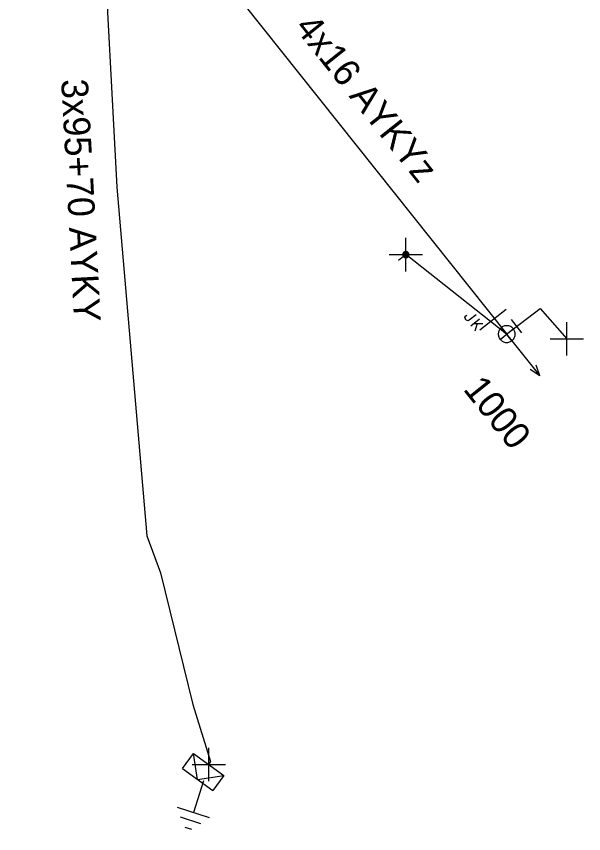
# Model space of a CAD drawing. Extents: x -540247 to -537390, y -1183887 to -1180355.
# Drawn here: x -537477.06 to -537455.83, y -1180665.57 to -1180635 of the extents above; entities that cross this region are included whole.
import ezdxf

# ---------------------------------------------------------------- set-up
doc = ezdxf.new("R2010")
doc.units = 0
for name, color, linetype in [('Vrstva 1', 7, 'Continuous'), ('Vrstva 13', 7, 'Continuous'), ('Vrstva 14', 7, 'Continuous'), ('Vrstva 15', 7, 'Continuous'), ('Vrstva 18', 7, 'Continuous'), ('Vrstva 2', 7, 'Continuous'), ('Vrstva 31', 7, 'Continuous'), ('Vrstva 34', 7, 'Continuous'), ('Vrstva 4', 7, 'Continuous'), ('Vrstva 52', 7, 'Continuous'), ('Vrstva 53', 7, 'Continuous'), ('Vrstva 54', 7, 'Continuous'), ('Vrstva 9', 7, 'Continuous')]:
    doc.layers.add(name, color=color, linetype=linetype)

# ---------------------------------------------------------------- blocks, each defined once
blk = doc.blocks.new('NN560')
at = {"layer": 'Vrstva 2'}
for points in [[(1.999, -0.001), (1.59, 0.141)], [(0, -0.001), (1.999, -0.001)], [(1.999, -0.001), (1.59, -0.134)]]:
    blk.add_lwpolyline(points, dxfattribs=at)
blk = doc.blocks.new('NN840')
at = {"layer": 'Vrstva 15'}
for points in [[(0.003, 0.619), (0.003, -0.631)], [(-0.538, -0.385), (-0.538, -0.71)], [(-0.332, -0.385), (-0.332, -0.798)], [(-0.332, -0.641), (-0.125, -0.385)], [(-0.263, -0.557), (-0.091, -0.798)], [(-0.745, -0.71), (-0.745, -0.66)], [(-0.73, -0.764), (-0.745, -0.71)], [(-0.657, -0.798), (-0.73, -0.764)], [(-0.627, -0.798), (-0.657, -0.798)], [(-0.558, -0.764), (-0.627, -0.798)], [(-0.538, -0.71), (-0.558, -0.764)]]:
    blk.add_lwpolyline(points, dxfattribs=at)
blk = doc.blocks.new('NN800')
at = {"layer": 'Vrstva 1'}
for points in [[(-0.442, 0.442), (0.442, -0.442)], [(-0.442, -0.442), (0.442, 0.442)]]:
    blk.add_lwpolyline(points, dxfattribs=at)
blk = doc.blocks.new('NN630')
at = {"layer": 'Vrstva 9'}
for points in [[(-0.003, -0.7), (-0.703, 0)], [(-0.703, -0.7), (-0.703, 0), (0.697, 0), (0.697, -0.7)], [(-0.003, -0.7), (0.697, 0)], [(-0.703, -0.7), (0.697, -0.7)]]:
    blk.add_lwpolyline(points, dxfattribs=at)
blk = doc.blocks.new('NN810')
at = {"layer": 'Vrstva 14'}
for points in [[(0.004, -0.64), (0.004, -1.89)], [(0.629, -1.89), (-0.621, -1.89)], [(0.388, -2.2), (-0.399, -2.2)], [(0.004, -2.515), (-0.124, -2.515)], [(0.137, -2.515), (0.004, -2.515)]]:
    blk.add_lwpolyline(points, dxfattribs=at)
blk = doc.blocks.new('NN500')
at = {"layer": 'Vrstva 2'}
for points in [[(-0.001, -0.235), (0.023, -0.234), (0.048, -0.23), (0.071, -0.224), (0.094, -0.215), (0.116, -0.204), (0.137, -0.191), (0.156, -0.175), (0.173, -0.158), (0.189, -0.139), (0.202, -0.118), (0.213, -0.096), (0.222, -0.073), (0.229, -0.049), (0.232, -0.025), (0.234, 0), (0.232, 0.024), (0.229, 0.048), (0.222, 0.072), (0.213, 0.095), (0.202, 0.117), (0.189, 0.138), (0.173, 0.157), (0.156, 0.174), (0.137, 0.19), (0.116, 0.203), (0.094, 0.214), (0.071, 0.223), (0.048, 0.229), (0.023, 0.233), (-0.001, 0.235), (-0.026, 0.233), (-0.05, 0.229), (-0.074, 0.223), (-0.097, 0.214), (-0.119, 0.203), (-0.139, 0.19), (-0.158, 0.174), (-0.176, 0.157), (-0.191, 0.138), (-0.205, 0.117), (-0.216, 0.095), (-0.225, 0.072), (-0.231, 0.048), (-0.235, 0.024), (-0.236, 0), (-0.235, -0.025), (-0.231, -0.049), (-0.225, -0.073), (-0.216, -0.096), (-0.205, -0.118), (-0.191, -0.139), (-0.176, -0.158), (-0.158, -0.175), (-0.139, -0.191), (-0.119, -0.204), (-0.097, -0.215), (-0.074, -0.224), (-0.05, -0.23), (-0.026, -0.234), (-0.001, -0.235)], [(-0.001, -0.235), (0.023, -0.234), (0.048, -0.23), (0.071, -0.224), (0.094, -0.215), (0.116, -0.204), (0.137, -0.191), (0.156, -0.175), (0.173, -0.158), (0.189, -0.139), (0.202, -0.118), (0.213, -0.096), (0.222, -0.073), (0.229, -0.049), (0.232, -0.025), (0.234, 0), (0.232, 0.024), (0.229, 0.048), (0.222, 0.072), (0.213, 0.095), (0.202, 0.117), (0.189, 0.138), (0.173, 0.157), (0.156, 0.174), (0.137, 0.19), (0.116, 0.203), (0.094, 0.214), (0.071, 0.223), (0.048, 0.229), (0.023, 0.233), (-0.001, 0.235), (-0.026, 0.233), (-0.05, 0.229), (-0.074, 0.223), (-0.097, 0.214), (-0.119, 0.203), (-0.139, 0.19), (-0.158, 0.174), (-0.176, 0.157), (-0.191, 0.138), (-0.205, 0.117), (-0.216, 0.095), (-0.225, 0.072), (-0.231, 0.048), (-0.235, 0.024), (-0.236, 0), (-0.235, -0.025), (-0.231, -0.049), (-0.225, -0.073), (-0.216, -0.096), (-0.205, -0.118), (-0.191, -0.139), (-0.176, -0.158), (-0.158, -0.175), (-0.139, -0.191), (-0.119, -0.204), (-0.097, -0.215), (-0.074, -0.224), (-0.05, -0.23), (-0.026, -0.234), (-0.001, -0.235)], [(-0.001, -0.206), (0.02, -0.205), (0.041, -0.201), (0.062, -0.196), (0.082, -0.188), (0.101, -0.178), (0.12, -0.167), (0.136, -0.153), (0.151, -0.138), (0.165, -0.121), (0.177, -0.103), (0.186, -0.084), (0.194, -0.064), (0.2, -0.043), (0.203, -0.022), (0.204, 0), (0.203, 0.021), (0.2, 0.042), (0.194, 0.063), (0.186, 0.083), (0.177, 0.102), (0.165, 0.12), (0.151, 0.137), (0.136, 0.152), (0.12, 0.166), (0.101, 0.177), (0.082, 0.187), (0.062, 0.195), (0.041, 0.2), (0.02, 0.204), (-0.001, 0.205), (-0.023, 0.204), (-0.044, 0.2), (-0.065, 0.195), (-0.085, 0.187), (-0.104, 0.177), (-0.122, 0.166), (-0.139, 0.152), (-0.154, 0.137), (-0.167, 0.12), (-0.179, 0.102), (-0.189, 0.083), (-0.197, 0.063), (-0.202, 0.042), (-0.205, 0.021), (-0.207, 0), (-0.205, -0.022), (-0.202, -0.043), (-0.197, -0.064), (-0.189, -0.084), (-0.179, -0.103), (-0.167, -0.121), (-0.154, -0.138), (-0.139, -0.153), (-0.122, -0.167), (-0.104, -0.178), (-0.085, -0.188), (-0.065, -0.196), (-0.044, -0.201), (-0.023, -0.205), (-0.001, -0.206)], [(-0.001, -0.176), (0.017, -0.175), (0.035, -0.172), (0.053, -0.168), (0.07, -0.161), (0.087, -0.153), (0.102, -0.143), (0.116, -0.131), (0.129, -0.118), (0.141, -0.104), (0.151, -0.088), (0.159, -0.072), (0.166, -0.055), (0.171, -0.037), (0.174, -0.019), (0.175, 0), (0.174, 0.018), (0.171, 0.036), (0.166, 0.054), (0.159, 0.071), (0.151, 0.087), (0.141, 0.103), (0.129, 0.117), (0.116, 0.13), (0.102, 0.142), (0.087, 0.152), (0.07, 0.16), (0.053, 0.167), (0.035, 0.172), (0.017, 0.174), (-0.001, 0.175), (-0.02, 0.174), (-0.038, 0.172), (-0.056, 0.167), (-0.073, 0.16), (-0.089, 0.152), (-0.105, 0.142), (-0.119, 0.13), (-0.132, 0.117), (-0.143, 0.103), (-0.153, 0.087), (-0.162, 0.071), (-0.168, 0.054), (-0.173, 0.036), (-0.176, 0.018), (-0.177, 0), (-0.176, -0.019), (-0.173, -0.037), (-0.168, -0.055), (-0.162, -0.072), (-0.153, -0.088), (-0.143, -0.104), (-0.132, -0.118), (-0.119, -0.131), (-0.105, -0.143), (-0.089, -0.153), (-0.073, -0.161), (-0.056, -0.168), (-0.038, -0.172), (-0.02, -0.175), (-0.001, -0.176)], [(-0.001, -0.147), (0.014, -0.146), (0.029, -0.143), (0.044, -0.139), (0.058, -0.134), (0.072, -0.127), (0.085, -0.119), (0.097, -0.109), (0.107, -0.098), (0.117, -0.086), (0.125, -0.073), (0.132, -0.06), (0.138, -0.046), (0.142, -0.031), (0.144, -0.016), (0.145, 0), (0.144, 0.015), (0.142, 0.03), (0.138, 0.045), (0.132, 0.059), (0.125, 0.073), (0.117, 0.086), (0.107, 0.097), (0.097, 0.108), (0.085, 0.118), (0.072, 0.126), (0.058, 0.133), (0.044, 0.139), (0.029, 0.143), (0.014, 0.145), (-0.001, 0.146), (-0.017, 0.145), (-0.032, 0.143), (-0.046, 0.139), (-0.061, 0.133), (-0.074, 0.126), (-0.087, 0.118), (-0.099, 0.108), (-0.11, 0.097), (-0.119, 0.086), (-0.128, 0.073), (-0.135, 0.059), (-0.14, 0.045), (-0.144, 0.03), (-0.147, 0.015), (-0.147, 0), (-0.147, -0.016), (-0.144, -0.031), (-0.14, -0.046), (-0.135, -0.06), (-0.128, -0.073), (-0.119, -0.086), (-0.11, -0.098), (-0.099, -0.109), (-0.087, -0.119), (-0.074, -0.127), (-0.061, -0.134), (-0.046, -0.139), (-0.032, -0.143), (-0.017, -0.146), (-0.001, -0.147)], [(-0.001, -0.117), (0.011, -0.116), (0.023, -0.114), (0.035, -0.111), (0.046, -0.107), (0.057, -0.101), (0.067, -0.095), (0.077, -0.087), (0.085, -0.078), (0.093, -0.069), (0.1, -0.059), (0.105, -0.048), (0.11, -0.036), (0.113, -0.025), (0.115, -0.013), (0.115, 0), (0.115, 0.012), (0.113, 0.024), (0.11, 0.036), (0.105, 0.047), (0.1, 0.058), (0.093, 0.068), (0.085, 0.078), (0.077, 0.086), (0.067, 0.094), (0.057, 0.101), (0.046, 0.106), (0.035, 0.11), (0.023, 0.114), (0.011, 0.116), (-0.001, 0.116), (-0.013, 0.116), (-0.025, 0.114), (-0.037, 0.11), (-0.049, 0.106), (-0.059, 0.101), (-0.07, 0.094), (-0.079, 0.086), (-0.088, 0.078), (-0.096, 0.068), (-0.102, 0.058), (-0.108, 0.047), (-0.112, 0.036), (-0.115, 0.024), (-0.117, 0.012), (-0.118, 0), (-0.117, -0.013), (-0.115, -0.025), (-0.112, -0.036), (-0.108, -0.048), (-0.102, -0.059), (-0.096, -0.069), (-0.088, -0.078), (-0.079, -0.087), (-0.07, -0.095), (-0.059, -0.101), (-0.049, -0.107), (-0.037, -0.111), (-0.025, -0.114), (-0.013, -0.116), (-0.001, -0.117)], [(-0.001, -0.087), (0.008, -0.087), (0.017, -0.085), (0.026, -0.083), (0.034, -0.08), (0.042, -0.076), (0.05, -0.071), (0.057, -0.065), (0.063, -0.059), (0.069, -0.051), (0.074, -0.044), (0.078, -0.036), (0.081, -0.027), (0.084, -0.019), (0.085, -0.01), (0.086, 0), (0.085, 0.009), (0.084, 0.018), (0.081, 0.026), (0.078, 0.035), (0.074, 0.043), (0.069, 0.051), (0.063, 0.058), (0.057, 0.064), (0.05, 0.07), (0.042, 0.075), (0.034, 0.079), (0.026, 0.082), (0.017, 0.085), (0.008, 0.086), (-0.001, 0.087), (-0.01, 0.086), (-0.019, 0.085), (-0.028, 0.082), (-0.037, 0.079), (-0.045, 0.075), (-0.052, 0.07), (-0.059, 0.064), (-0.066, 0.058), (-0.072, 0.051), (-0.077, 0.043), (-0.081, 0.035), (-0.084, 0.026), (-0.086, 0.018), (-0.088, 0.009), (-0.088, 0), (-0.088, -0.01), (-0.086, -0.019), (-0.084, -0.027), (-0.081, -0.036), (-0.077, -0.044), (-0.072, -0.052), (-0.066, -0.059), (-0.059, -0.065), (-0.052, -0.071), (-0.045, -0.076), (-0.037, -0.08), (-0.028, -0.083), (-0.019, -0.085), (-0.01, -0.087), (-0.001, -0.087)], [(-0.001, -0.058), (0.005, -0.057), (0.011, -0.056), (0.016, -0.055), (0.022, -0.053), (0.027, -0.05), (0.032, -0.047), (0.037, -0.043), (0.041, -0.039), (0.045, -0.034), (0.048, -0.029), (0.051, -0.024), (0.053, -0.018), (0.055, -0.012), (0.056, -0.006), (0.056, 0), (0.056, 0.006), (0.055, 0.011), (0.053, 0.017), (0.051, 0.023), (0.048, 0.028), (0.045, 0.033), (0.041, 0.038), (0.037, 0.042), (0.032, 0.046), (0.027, 0.049), (0.022, 0.052), (0.016, 0.054), (0.011, 0.056), (0.005, 0.057), (-0.001, 0.057), (-0.007, 0.057), (-0.013, 0.056), (-0.019, 0.054), (-0.025, 0.052), (-0.03, 0.049), (-0.035, 0.046), (-0.04, 0.042), (-0.044, 0.038), (-0.048, 0.033), (-0.051, 0.028), (-0.054, 0.023), (-0.056, 0.017), (-0.057, 0.011), (-0.058, 0.006), (-0.059, 0), (-0.058, -0.006), (-0.057, -0.012), (-0.056, -0.018), (-0.054, -0.024), (-0.051, -0.029), (-0.048, -0.034), (-0.044, -0.039), (-0.04, -0.043), (-0.035, -0.047), (-0.03, -0.05), (-0.025, -0.053), (-0.019, -0.055), (-0.013, -0.056), (-0.007, -0.057), (-0.001, -0.058)], [(-0.001, -0.028), (0.002, -0.028), (0.005, -0.028), (0.007, -0.027), (0.01, -0.026), (0.013, -0.024), (0.015, -0.023), (0.017, -0.021), (0.019, -0.019), (0.021, -0.017), (0.023, -0.014), (0.024, -0.012), (0.025, -0.009), (0.026, -0.006), (0.026, -0.003), (0.027, 0), (0.026, 0.002), (0.026, 0.005), (0.025, 0.008), (0.024, 0.011), (0.023, 0.013), (0.021, 0.016), (0.019, 0.018), (0.017, 0.02), (0.015, 0.022), (0.013, 0.024), (0.01, 0.025), (0.007, 0.026), (0.005, 0.027), (0.002, 0.027), (-0.001, 0.027), (-0.004, 0.027), (-0.007, 0.027), (-0.01, 0.026), (-0.012, 0.025), (-0.015, 0.024), (-0.018, 0.022), (-0.02, 0.02), (-0.022, 0.018), (-0.024, 0.016), (-0.025, 0.013), (-0.027, 0.011), (-0.028, 0.008), (-0.028, 0.005), (-0.029, 0.002), (-0.029, 0), (-0.029, -0.003), (-0.028, -0.006), (-0.028, -0.009), (-0.027, -0.012), (-0.025, -0.014), (-0.024, -0.017), (-0.022, -0.019), (-0.02, -0.021), (-0.018, -0.023), (-0.015, -0.024), (-0.012, -0.026), (-0.01, -0.027), (-0.007, -0.028), (-0.004, -0.028), (-0.001, -0.028)], [(0.234, 0), (0.704, 0)]]:
    blk.add_lwpolyline(points, dxfattribs=at)
blk = doc.blocks.new('NN410')
at = {"layer": 'Vrstva 2'}
for points in [[(0.005, 0.632), (-0.061, 0.628), (-0.126, 0.618), (-0.19, 0.601), (-0.251, 0.577), (-0.31, 0.547), (-0.365, 0.511), (-0.416, 0.47), (-0.463, 0.423), (-0.505, 0.372), (-0.541, 0.317), (-0.57, 0.258), (-0.594, 0.196), (-0.611, 0.133), (-0.621, 0.068), (-0.625, 0.002), (-0.621, -0.064), (-0.611, -0.129), (-0.594, -0.193), (-0.57, -0.254), (-0.541, -0.313), (-0.505, -0.368), (-0.463, -0.42), (-0.416, -0.466), (-0.365, -0.508), (-0.31, -0.544), (-0.251, -0.574), (-0.19, -0.597), (-0.126, -0.614), (-0.061, -0.625), (0.005, -0.628), (0.071, -0.625), (0.136, -0.614), (0.2, -0.597), (0.261, -0.574), (0.32, -0.544), (0.375, -0.508), (0.427, -0.466), (0.473, -0.42), (0.515, -0.368), (0.55, -0.313), (0.581, -0.254), (0.604, -0.193), (0.621, -0.129), (0.632, -0.064), (0.635, 0.002), (0.632, 0.068), (0.621, 0.133), (0.604, 0.196), (0.58, 0.258), (0.55, 0.317), (0.515, 0.372), (0.473, 0.423), (0.427, 0.47), (0.375, 0.511), (0.32, 0.547), (0.261, 0.577), (0.2, 0.601), (0.136, 0.618), (0.071, 0.628), (0.005, 0.632)], [(0.004, -0.631), (0.004, 0.629)], [(0.958, -0.631), (0.958, 0.629)], [(-0.626, -0.001), (0.633, -0.001)]]:
    blk.add_lwpolyline(points, dxfattribs=at)

msp = doc.modelspace()

# ---------------------------------------------------------------- linework, layer by layer
at = {"layer": 'Vrstva 4'}
msp.add_lwpolyline([(-537458.713, -1180646.885), (-537462.487, -1180643.911)], dxfattribs=at)
at = {"layer": 'Vrstva 52'}
for points in [[(-537475.729, -1180601.74), (-537473.65, -1180602.83), (-537471.84, -1180604.05), (-537471.24, -1180605.97), (-537472.34, -1180610.21), (-537474.88, -1180618.16), (-537477.06, -1180625.37), (-537476.38, -1180629.35), (-537474.45, -1180630.62), (-537473.84, -1180631.33), (-537473.3, -1180641.39), (-537472.18, -1180654.43), (-537471.67, -1180655.81), (-537470.45, -1180660.74), (-537469.79, -1180662.87), (-537469.862, -1180662.98)], [(-537470.662, -1180631.873), (-537458.712, -1180646.885)], [(-537458.713, -1180646.885), (-537457.456, -1180645.926), (-537456.457, -1180647.064)]]:
    msp.add_lwpolyline(points, dxfattribs=at)

# ---------------------------------------------------------------- block references
at = {"layer": 'Vrstva 13'}
for name, p, xscale, yscale, rotation in [('NN500', (-537462.487, -1180643.912), 0.49999999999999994, 0.5000000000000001, -140.60300009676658), ('NN410', (-537458.713, -1180646.885), 0.5, 0.5, 38.521433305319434)]:
    msp.add_blockref(name, p, dxfattribs=dict(at, xscale=xscale, yscale=yscale, rotation=rotation))
at = {"layer": 'Vrstva 13', "rotation": -51.47856669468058}
msp.add_blockref('NN560', (-537458.713, -1180646.885), dxfattribs=at)
at = {"layer": 'Vrstva 15', "rotation": -17.71851665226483}
msp.add_blockref('NN810', (-537469.862, -1180662.981), dxfattribs=at)
at = {"layer": 'Vrstva 18', "rotation": -51.47856674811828}
msp.add_blockref('NN840', (-537459.221, -1180646.345), dxfattribs=at)
at = {"layer": 'Vrstva 31', "rotation": -36.02361665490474}
msp.add_blockref('NN630', (-537469.862, -1180662.98), dxfattribs=at)
at = {"layer": 'Vrstva 34', "rotation": 45}
for p in [(-537462.487, -1180643.911), (-537456.457, -1180647.064), (-537469.862, -1180662.98)]:
    msp.add_blockref('NN800', p, dxfattribs=at)

# ---------------------------------------------------------------- texts
at = {"layer": 'Vrstva 14'}
msp.add_text('1000', height=1, rotation=308.521, dxfattribs=at).set_placement((-537460.369, -1180648.951))
at = {"layer": 'Vrstva 53'}
msp.add_text('4x16 AYKYz', height=1, rotation=308.521, dxfattribs=at).set_placement((-537466.673, -1180635.425))
at = {"layer": 'Vrstva 54'}
msp.add_text('3x95+70 AYKY', height=1, rotation=273.073, dxfattribs=at).set_placement((-537475.385, -1180637.362))

doc.saveas('drawing.dxf')
